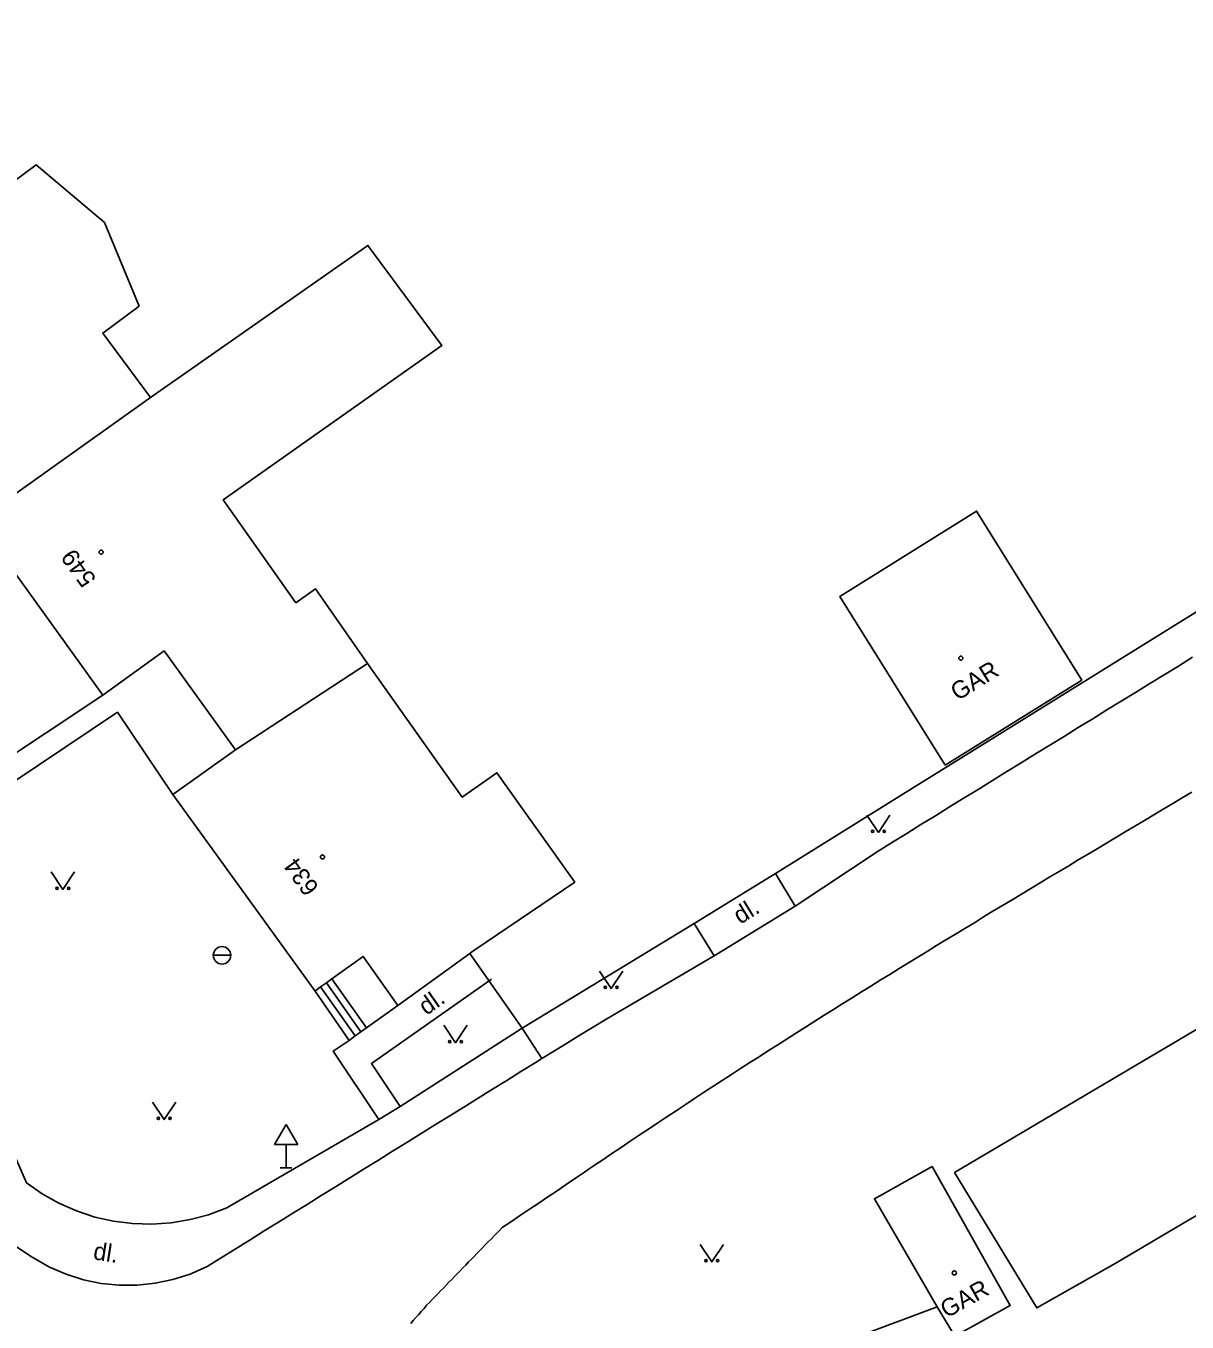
# Model space of a CAD drawing. Extents: x -536391 to -535419, y -1201788 to -1200779.
# Drawn here: x -535548.5 to -535498.7, y -1201544.3 to -1201488.6 of the extents above; entities that cross this region are included whole.
import ezdxf

# ---------------------------------------------------------------- set-up
doc = ezdxf.new("R2010")
doc.units = 0
for name, color, linetype in [('CIZÍ_NADZEM_POPIS', 7, 'Continuous'), ('CIZÍ_PODZEM', 7, 'Continuous'), ('CIZÍ_PODZEM_POPIS', 7, 'Continuous'), ('POL_ZNAČKA_PRACOVNÍ', 7, 'Continuous'), ('SDEL_EON', 7, 'Continuous'), ('SDEL_EON_POPIS', 7, 'Continuous'), ('TECH_OCHR_PÁSMO_HRAN', 7, 'Continuous'), ('ZP_EON', 7, 'Continuous')]:
    doc.layers.add(name, color=color, linetype=linetype)

msp = doc.modelspace()

# ---------------------------------------------------------------- linework, layer by layer
at = {"layer": 'CIZÍ_PODZEM'}
for centre in [(-535545.29, -1201511.22), (-535508.39, -1201515.77), (-535535.79, -1201524.3), (-535508.67, -1201542.15)]:
    msp.add_circle(centre, 0.0875, dxfattribs=at)
at = {"layer": 'CIZÍ_PODZEM_POPIS'}
for p, q in [((-535540.475, -1201528.52), (-535539.725, -1201528.52)), ((-535537.35, -1201535.774), (-535537.85, -1201536.64)), ((-535537.35, -1201535.774), (-535536.85, -1201536.64)), ((-535537.85, -1201536.64), (-535536.85, -1201536.64)), ((-535537.35, -1201537.64), (-535537.35, -1201536.64)), ((-535537.6, -1201537.64), (-535537.1, -1201537.64))]:
    msp.add_line(p, q, dxfattribs=at)
for points in [[(-535467.2, -1201488.64), (-535464.59, -1201492.87), (-535510.99, -1201521.68)], [(-535510.99, -1201521.68), (-535516.35, -1201525.01), (-535519.84, -1201527.16), (-535527.22, -1201531.64)], [(-535527.22, -1201531.64), (-535529.47, -1201528.44)], [(-535509.4, -1201543.6), (-535512.88, -1201544.9), (-535514.03, -1201548.76)]]:
    msp.add_lwpolyline(points, dxfattribs=at)
msp.add_circle((-535540.1, -1201528.52), 0.375, dxfattribs=at)
at = {"layer": 'SDEL_EON'}
for points in [[(-535512.43, -1201522.5), (-535511.93, -1201523.25), (-535511.43, -1201522.5)], [(-535547.43, -1201524.94), (-535546.93, -1201525.69), (-535546.43, -1201524.94)], [(-535523.9, -1201529.2), (-535523.4, -1201529.95), (-535522.9, -1201529.2)], [(-535530.58, -1201531.52), (-535530.08, -1201532.27), (-535529.58, -1201531.52)], [(-535543.08, -1201534.82), (-535542.58, -1201535.57), (-535542.08, -1201534.82)], [(-535519.58, -1201540.93), (-535519.08, -1201541.68), (-535518.58, -1201540.93)]]:
    msp.add_lwpolyline(points, dxfattribs=at)
for centre in [(-535512.18, -1201523.2), (-535511.68, -1201523.2), (-535547.18, -1201525.64), (-535546.68, -1201525.64), (-535523.65, -1201529.9), (-535523.15, -1201529.9), (-535530.33, -1201532.22), (-535529.83, -1201532.22), (-535542.83, -1201535.52), (-535542.33, -1201535.52), (-535519.33, -1201541.63), (-535518.83, -1201541.63)]:
    msp.add_circle(centre, 0.05, dxfattribs=at)
at = {"layer": 'SDEL_EON_POPIS'}
for points in [[(-535508.66, -1201537.84), (-535452.84, -1201504.86)], [(-535550.61, -1201509.88), (-535545.22, -1201517.36), (-535542.59, -1201515.46), (-535539.52, -1201519.7)], [(-535509.06, -1201520.36), (-535503.2, -1201516.71)], [(-535539.52, -1201519.7), (-535542.21, -1201521.62), (-535536.11, -1201530.06)], [(-535532.56, -1201530.68), (-535529.47, -1201528.44)], [(-535529.47, -1201528.44), (-535529.39, -1201528.39)], [(-535529.39, -1201528.39), (-535529.25, -1201528.29)], [(-535535.39, -1201529.53), (-535534.05, -1201528.57), (-535532.56, -1201530.68)], [(-535535.62, -1201529.7), (-535535.39, -1201529.53)], [(-535536.11, -1201530.06), (-535535.87, -1201529.88)], [(-535535.87, -1201529.88), (-535535.62, -1201529.7)], [(-535509.4, -1201543.6), (-535512.1, -1201538.97), (-535509.62, -1201537.58)]]:
    msp.add_lwpolyline(points, dxfattribs=at)
at = {"layer": 'TECH_OCHR_PÁSMO_HRAN'}
for points in [[(-535498.44, -1201515.73), (-535499.05, -1201516.11), (-535499.66, -1201516.48), (-535500.28, -1201516.86), (-535500.89, -1201517.24), (-535501.51, -1201517.62), (-535502.12, -1201517.99), (-535502.73, -1201518.37), (-535503.35, -1201518.75), (-535503.96, -1201519.13), (-535504.57, -1201519.51), (-535505.19, -1201519.88), (-535505.8, -1201520.26), (-535506.41, -1201520.64), (-535507.03, -1201521.02), (-535507.64, -1201521.4), (-535508.25, -1201521.77), (-535508.87, -1201522.15), (-535509.48, -1201522.53), (-535510.1, -1201522.91), (-535510.71, -1201523.29), (-535511.32, -1201523.67), (-535511.94, -1201524.05), (-535515.5, -1201526.41)], [(-535555.04, -1201523.88), (-535545.22, -1201517.36)], [(-535554.6, -1201524.8), (-535544.59, -1201518.09), (-535542.21, -1201521.62)], [(-535498.48, -1201521.52), (-535498.89, -1201521.77), (-535499.29, -1201522.01), (-535499.7, -1201522.25), (-535500.11, -1201522.49), (-535500.51, -1201522.74), (-535500.92, -1201522.98), (-535501.33, -1201523.22), (-535501.73, -1201523.46), (-535502.14, -1201523.71), (-535502.54, -1201523.95), (-535502.95, -1201524.19), (-535503.36, -1201524.43), (-535503.76, -1201524.68), (-535504.17, -1201524.92), (-535504.57, -1201525.16), (-535504.98, -1201525.41), (-535505.39, -1201525.65), (-535505.79, -1201525.9), (-535506.19, -1201526.14), (-535506.6, -1201526.38), (-535507.01, -1201526.63), (-535507.41, -1201526.87), (-535507.81, -1201527.12), (-535508.22, -1201527.37), (-535508.62, -1201527.61), (-535509.03, -1201527.86), (-535509.43, -1201528.1), (-535509.83, -1201528.35), (-535510.24, -1201528.6), (-535510.64, -1201528.85), (-535511.04, -1201529.09), (-535511.44, -1201529.34), (-535511.85, -1201529.59), (-535512.25, -1201529.84), (-535512.65, -1201530.09), (-535513.05, -1201530.34), (-535513.45, -1201530.59), (-535513.85, -1201530.84), (-535514.26, -1201531.09), (-535514.66, -1201531.34), (-535515.06, -1201531.6), (-535515.45, -1201531.85), (-535515.85, -1201532.1), (-535516.25, -1201532.36), (-535516.65, -1201532.61)], [(-535533.37, -1201535.56), (-535539.82, -1201539.32), (-535539.9, -1201539.36), (-535540.68, -1201539.65), (-535541.47, -1201539.86), (-535542.29, -1201540), (-535543.11, -1201540.06), (-535543.94, -1201540.03), (-535544.76, -1201539.93), (-535545.56, -1201539.75), (-535546.35, -1201539.49), (-535547.1, -1201539.16), (-535547.82, -1201538.75), (-535548.5, -1201538.28), (-535551.9, -1201530.48), (-535554.6, -1201524.8)], [(-535515.5, -1201526.41), (-535516.35, -1201525.01)], [(-535515.5, -1201526.41), (-535518.98, -1201528.55)], [(-535518.98, -1201528.55), (-535519.84, -1201527.16)], [(-535518.98, -1201528.55), (-535523.59, -1201531.24), (-535524.2, -1201531.62), (-535524.81, -1201531.99), (-535525.43, -1201532.37), (-535526.04, -1201532.75), (-535526.37, -1201532.95)], [(-535535.39, -1201529.53), (-535533.9, -1201531.63)], [(-535528.53, -1201529.55), (-535533.69, -1201533.17), (-535532.46, -1201535.01)], [(-535536.11, -1201530.06), (-535534.65, -1201532.18), (-535534.39, -1201531.97)], [(-535535.87, -1201529.88), (-535534.39, -1201531.97)], [(-535535.62, -1201529.7), (-535534.15, -1201531.8)], [(-535533.9, -1201531.63), (-535532.56, -1201530.68)], [(-535534.39, -1201531.97), (-535534.15, -1201531.8)], [(-535534.15, -1201531.8), (-535533.9, -1201531.63)], [(-535527.22, -1201531.64), (-535532.46, -1201535.01)], [(-535526.37, -1201532.95), (-535527.22, -1201531.64)], [(-535534.65, -1201532.18), (-535535.33, -1201532.63), (-535533.37, -1201535.56)], [(-535526.37, -1201532.95), (-535526.66, -1201533.13), (-535527.27, -1201533.51), (-535527.88, -1201533.89), (-535528.49, -1201534.27), (-535529.11, -1201534.65), (-535529.72, -1201535.03), (-535530.33, -1201535.41), (-535530.94, -1201535.78), (-535531.56, -1201536.17), (-535532.17, -1201536.55), (-535532.78, -1201536.93), (-535533.39, -1201537.31), (-535534, -1201537.69), (-535534.61, -1201538.07), (-535535.23, -1201538.45), (-535535.84, -1201538.83), (-535536.45, -1201539.21), (-535537.06, -1201539.59), (-535537.68, -1201539.97), (-535538.29, -1201540.35), (-535538.9, -1201540.73), (-535540.74, -1201541.87), (-535541.47, -1201542.2), (-535542.21, -1201542.43), (-535542.97, -1201542.59), (-535543.74, -1201542.68), (-535544.52, -1201542.68), (-535545.29, -1201542.6), (-535546.05, -1201542.44), (-535546.79, -1201542.21), (-535547.5, -1201541.9), (-535548.32, -1201541.43), (-535549.11, -1201540.9)], [(-535516.65, -1201532.61), (-535517.05, -1201532.87), (-535517.45, -1201533.12), (-535517.84, -1201533.38), (-535518.24, -1201533.64), (-535518.64, -1201533.89), (-535519.03, -1201534.15), (-535519.43, -1201534.41), (-535519.82, -1201534.67), (-535520.22, -1201534.93), (-535520.61, -1201535.19), (-535521.01, -1201535.45), (-535521.4, -1201535.71), (-535521.8, -1201535.98), (-535522.19, -1201536.24), (-535522.58, -1201536.5), (-535522.97, -1201536.77), (-535523.37, -1201537.03), (-535523.76, -1201537.3), (-535524.15, -1201537.56), (-535524.54, -1201537.82), (-535524.93, -1201538.09), (-535525.33, -1201538.35), (-535525.72, -1201538.62), (-535526.11, -1201538.88), (-535526.5, -1201539.15), (-535526.9, -1201539.41), (-535527.29, -1201539.67), (-535527.68, -1201539.94), (-535528.07, -1201540.2), (-535528.19, -1201540.33), (-535528.31, -1201540.45), (-535528.43, -1201540.57), (-535528.55, -1201540.7), (-535528.68, -1201540.82), (-535528.8, -1201540.94), (-535528.92, -1201541.07), (-535529.04, -1201541.19), (-535529.16, -1201541.31), (-535529.28, -1201541.44), (-535529.4, -1201541.56), (-535529.52, -1201541.68), (-535529.64, -1201541.81), (-535529.76, -1201541.93), (-535529.88, -1201542.06), (-535530, -1201542.18), (-535530.12, -1201542.3), (-535530.24, -1201542.43), (-535530.36, -1201542.55), (-535530.48, -1201542.67), (-535530.6, -1201542.8), (-535530.72, -1201542.92), (-535530.84, -1201543.04), (-535530.96, -1201543.17), (-535531.08, -1201543.29), (-535531.2, -1201543.42), (-535531.32, -1201543.54), (-535531.43, -1201543.67), (-535531.55, -1201543.8), (-535531.66, -1201543.93), (-535531.78, -1201544.06), (-535531.89, -1201544.19), (-535532, -1201544.32)], [(-535532.46, -1201535.01), (-535533.37, -1201535.56)]]:
    msp.add_lwpolyline(points, dxfattribs=at)
at = {"layer": 'ZP_EON'}
for points in [[(-535543.17, -1201504.58), (-535545.22, -1201501.82), (-535543.66, -1201500.66), (-535545.15, -1201497.07), (-535548.08, -1201494.6), (-535549.58, -1201495.71), (-535551.65, -1201492.83), (-535559.12, -1201498.12)], [(-535533.86, -1201516), (-535536.09, -1201512.79), (-535536.93, -1201513.39), (-535540.05, -1201508.98), (-535530.66, -1201502.35), (-535533.84, -1201498.06), (-535543.17, -1201504.58), (-535550.61, -1201509.88)], [(-535508.66, -1201537.84), (-535505.13, -1201543.65), (-535501.77, -1201541.75), (-535498.54, -1201539.84), (-535498.42, -1201539.77), (-535495.44, -1201538), (-535492.35, -1201536.17), (-535491.12, -1201535.44), (-535489.25, -1201534.34), (-535486.15, -1201532.5), (-535482.92, -1201530.59), (-535479.86, -1201528.78), (-535476.81, -1201526.97), (-535473.75, -1201525.16), (-535470.7, -1201523.36), (-535467.64, -1201521.55), (-535464.59, -1201519.74), (-535461.53, -1201517.93), (-535458.48, -1201516.12), (-535455.42, -1201514.31), (-535452.37, -1201512.51), (-535449.32, -1201510.7), (-535452.84, -1201504.86)], [(-535503.2, -1201516.71), (-535507.71, -1201509.46), (-535513.59, -1201513.13), (-535509.06, -1201520.36)], [(-535533.86, -1201516), (-535539.52, -1201519.7)], [(-535529.25, -1201528.29), (-535524.96, -1201525.38), (-535528.3, -1201520.69), (-535529.79, -1201521.74), (-535533.86, -1201516)], [(-535509.4, -1201543.6), (-535508.65, -1201544.87), (-535506.27, -1201543.55), (-535509.62, -1201537.58)]]:
    msp.add_lwpolyline(points, dxfattribs=at)

# ---------------------------------------------------------------- texts
at = {"layer": 'CIZÍ_NADZEM_POPIS'}
for s, rotation, p in [('549', 125.82, (-535545.47, -1201512.37)), ('634', 125.84, (-535535.91, -1201525.61))]:
    msp.add_text(s, height=0.75, rotation=rotation, dxfattribs=at).set_placement(p)
at = {"layer": 'POL_ZNAČKA_PRACOVNÍ'}
for s, rotation, p in [('GAR', 31.88, (-535508.53, -1201517.62)), ('dl.', 31.71, (-535517.86, -1201527.21)), ('dl.', 35.05, (-535531.33, -1201531.12)), ('dl.', 351.09, (-535545.66, -1201541.56)), ('GAR', 29.28, (-535509, -1201544.11))]:
    msp.add_text(s, height=0.75, rotation=rotation, dxfattribs=at).set_placement(p)

doc.saveas('drawing.dxf')
